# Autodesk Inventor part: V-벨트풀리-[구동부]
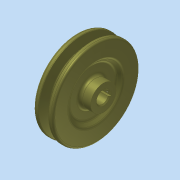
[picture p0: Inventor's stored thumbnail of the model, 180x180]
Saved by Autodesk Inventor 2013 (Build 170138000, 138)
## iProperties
Company: 한국ATC센터
Created: 2014-02
Part Number: V-벨트풀리-[구동부]
Document SubType Name: Modeling
Designer: KYOUNG IL JANG
Density: 7.25 g/cm^3
Mass: 594.644 g
Surface Area: 210.328 cm^2
Volume: 82.0198 cm^3
Material: 주철
Vendor: CBT Solutions
Author: KYOUNG IL JANG
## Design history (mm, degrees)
sketch "스케치1"
  geometry: L1 (-13, 0)-(13, 0); L2 (-13, 0)-(-13, 12.5); L3 (-13, 12.5)-(-9, 12.5); L4 (-9, 12.5)-(-9, 23); L5 (-9, 23)-(-13, 27); L6 (-13, 27)-(-13, 42.7); L7 (-13, 42.7)-(-8.325, 42.7); L8 (-8.325, 42.7)-(-5.574, 33.7); L9 (-5.574, 33.7)-(-1.426, 33.7); L10 (-1.426, 33.7)-(1.325, 42.7); L11 (1.325, 42.7)-(6, 42.7); L12 (6, 42.7)-(6, 27); L13 (6, 27)-(2, 23); L14 (2, 23)-(2, 12.5); L15 (2, 12.5)-(13, 12.5); L16 (13, 12.5)-(13, 0); L17 (-7.5, 40)-(0.5, 40); 2 further points
  constraints: 34 end point, 6 parallel, 5 collinear, 5 equal length, 4 perpendicular, 2 point on line, 1 coincident, 1 horizontal, 1 midpoint
  dimensions: "d0" = 26 distance of L1.start L1.end; "d1" = 2.7 distance between parallel lines of L7 L17; "d2" = 6.3 distance between parallel lines of L9 L17; "d3" = 8 distance of L17.start L17.end; "d4" = 34 deg angle of L10 L8; "d5" = 19 distance between parallel lines of L12 L6; "d7" = 25 diameter of L15 L1; "d8" = 46 diameter of L13.end L1; "d9" = 54 diameter of L12.end L1; "d10" = 4 distance between parallel lines of L2 L4; "d11" = 80 diameter of L17 L1
revolve "회전1" sketch "스케치1" stored, may be unused: angle "d12" = 90 deg
sketch "스케치2"
  geometry: L1 (-2, 5.657)-(-2, 7.8); L2 (-2, 7.8)-(2, 7.8); L3 (2, 7.8)-(2, 5.657); A1 r 6 centre (0, 0) between (-2, 5.657) and (2, 5.657); 1 further point
  constraints: 6 end point, 2 parallel, 2 point on circle, 1 centre point, 1 coincident, 1 perpendicular, 1 vertical
  dimensions: "d13" = 12 diameter of A1; "d14" = 13.8 dimension on A1 L2; "d15" = 4 distance of L1.end L2.end
extrude "돌출1" cut sketch "스케치2" stored distance "d16" = 10; taper "d17" = 0 deg
node "작업 평면1"
sketch "스케치3"
  geometry: L1 (-5.5, 12.5)-(-5.5, -12.5) reference; 3 further points
  constraints: 1 horizontal alignment, 1 midpoint
  dimensions: "d18" = 4 distance from line of point (-1.5, 0) L1
hole "구멍1" sketch "스케치3" at (-1.5, 0) diameter "d19" = 2.459; stored, may be unused: countersink angle "d23" = 90 deg, drill point angle "d25" = 118 deg; dims "d20" = 6, "d21" = 4, "d22" = 2, "d24" = 8
fillet "모깎기1" dims "d26" = 2, "d27" = 0.5, "d28" = 1, "d29" = 3
chamfer "모따기1" distance "d30" = 1; stored, may be unused: second distance "d31" = 2, angle "d32" = 45 deg
node "솔리드1"
